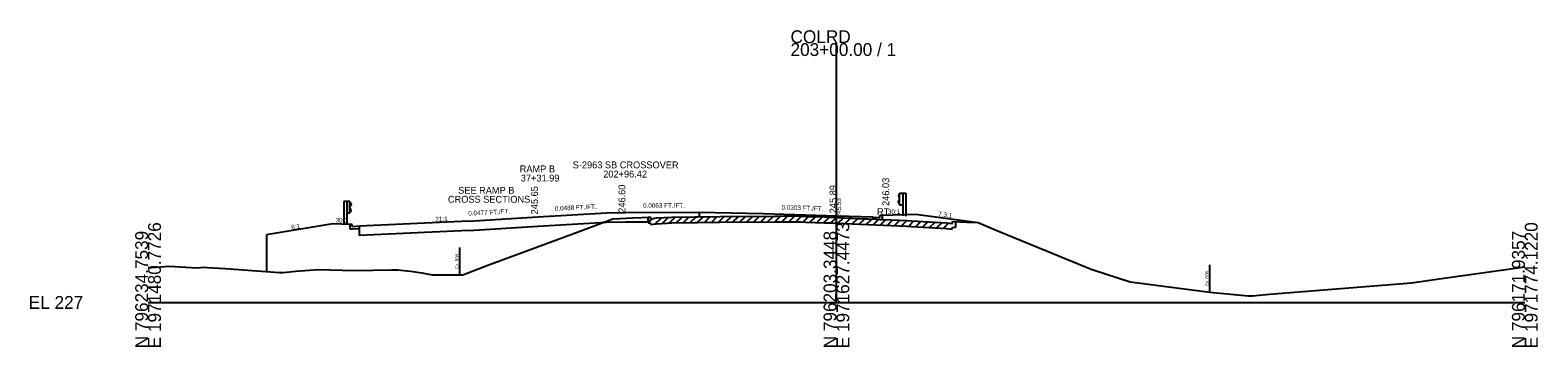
# Model space of a CAD drawing. Extents: x -26 to 1971520, y -10 to 796285.
# Drawn here: x 1274.3 to 1602.8, y 990.3 to 1059.4 of the extents above; entities that cross this region are included whole.
import ezdxf

# ---------------------------------------------------------------- set-up
doc = ezdxf.new("R2010")
doc.units = 0
for name, color, linetype in [('RD_GPK_XS_Cell', 7, 'Continuous'), ('RD_XS_Base', 7, 'Continuous'), ('RD_XS_CurbBase', 7, 'Continuous'), ('RD_XS_CurbTop', 7, 'Continuous'), ('RD_XS_ExGround', 7, 'Continuous'), ('RD_XS_ExPaveRet', 7, 'Continuous'), ('RD_XS_ExRW', 7, 'Continuous'), ('RD_XS_GR', 7, 'Continuous'), ('RD_XS_Misc_Line', 7, 'Continuous'), ('RD_XS_Pave', 7, 'Continuous'), ('RD_XS_PaveOvlay', 7, 'Continuous'), ('RD_XS_PaveShd', 7, 'Continuous'), ('RD_XS_TieSlope', 7, 'Continuous'), ('RD_XS_TX_Elev_EX', 7, 'Continuous'), ('RD_XS_TX_Elev_PR', 7, 'Continuous'), ('RD_XS_TX_MkPT', 7, 'Continuous'), ('RD_XS_TX_Notes', 7, 'Continuous'), ('RD_XS_TX_Profile', 7, 'Continuous'), ('RD_XS_TX_Slope', 7, 'Continuous'), ('RD_XS_TX_Station', 7, 'Continuous'), ('RD_XS_TX_TOC', 7, 'Continuous')]:
    doc.layers.add(name, color=color, linetype=linetype)

msp = doc.modelspace()

# ---------------------------------------------------------------- linework, layer by layer
at = {"layer": 'RD_GPK_XS_Cell'}
for p, q in [((1450, 1000), (1450, 1056.54)), ((1300, 1000), (1450, 1000)), ((1450, 1000), (1600, 1000))]:
    msp.add_line(p, q, dxfattribs=at)
at = {"layer": 'RD_XS_Base'}
for p, q in [((1458, 1018.62), (1458, 1018.64)), ((1458, 1018.12), (1458, 1018.62)), ((1345.99, 1016.6), (1345.99, 1016.62)), ((1345.99, 1016.1), (1345.99, 1016.6)), ((1345.99, 1016.6), (1345.99, 1014.56)), ((1369.9, 1015.7), (1345.99, 1014.56)), ((1369.9, 1015.7), (1384.96, 1016.61)), ((1384.96, 1016.61), (1399.89, 1017.51)), ((1399.89, 1017.51), (1404.01, 1017.56)), ((1404.01, 1017.56), (1408.95, 1017.59))]:
    msp.add_line(p, q, dxfattribs=at)
at = {"layer": 'RD_XS_CurbBase'}
for p, q in [((1460, 1019.04), (1460, 1018.04)), ((1343.99, 1017.02), (1343.99, 1016.02)), ((1343.99, 1016.02), (1344.57, 1016.02)), ((1344.57, 1016.02), (1345.99, 1016.1)), ((1459.42, 1018.04), (1458, 1018.12)), ((1460, 1018.04), (1459.42, 1018.04))]:
    msp.add_line(p, q, dxfattribs=at)
at = {"layer": 'RD_XS_CurbTop'}
for p, q in [((1458, 1018.64), (1458, 1018.62)), ((1458, 1018.62), (1459.42, 1018.54)), ((1459.42, 1018.54), (1459.5, 1019.04)), ((1459.5, 1019.04), (1460, 1019.04)), ((1344.49, 1017.02), (1343.99, 1017.02)), ((1344.57, 1016.52), (1344.49, 1017.02)), ((1345.99, 1016.6), (1344.57, 1016.52)), ((1345.99, 1016.62), (1345.99, 1016.6))]:
    msp.add_line(p, q, dxfattribs=at)
at = {"layer": 'RD_XS_ExGround'}
msp.add_lwpolyline([(1300, 1007.6), (1300.74, 1007.61), (1304.66, 1007.92), (1310.64, 1007.52), (1312.39, 1007.69), (1312.98, 1007.65), (1316.8, 1007.4), (1328.63, 1006.55), (1329.06, 1006.53), (1329.42, 1006.54), (1332.21, 1006.81), (1337.13, 1007.2), (1345.01, 1006.96), (1353.01, 1007.09), (1354.34, 1007.09), (1357.22, 1006.84), (1359.64, 1006.46), (1361.94, 1006.01), (1365.83, 1005.98), (1368.61, 1006), (1374.03, 1008.09), (1393.7, 1015.4), (1401.31, 1018.24), (1405.6, 1018.44), (1409.45, 1018.61), (1409.55, 1018.21), (1410.03, 1018.29), (1410.76, 1018.41), (1414.12, 1018.58), (1419.14, 1018.67), (1419.71, 1018.69), (1424.59, 1018.72), (1436.64, 1018.8), (1437.25, 1018.81), (1440.59, 1018.85), (1442.29, 1018.8), (1443.31, 1018.76), (1447.38, 1018.64), (1448.05, 1018.62), (1448.73, 1018.59), (1450, 1018.53), (1465.33, 1017.85), (1466.37, 1017.79), (1474.05, 1017.38), (1475.21, 1017.23), (1475.32, 1017.63), (1478.38, 1017.51), (1480.89, 1017.41), (1484.43, 1015.88), (1505.51, 1007.25), (1513.97, 1004.48), (1530.3, 1002.35), (1531.4, 1002.22), (1539.74, 1001.45), (1540.15, 1001.43), (1540.69, 1001.43), (1544.38, 1001.82), (1575.33, 1004.29), (1581.31, 1005.16), (1600, 1007.74)], dxfattribs=at)
at = {"layer": 'RD_XS_ExPaveRet'}
for p, q in [((1408.95, 1017.34), (1408.95, 1018.59)), ((1408.95, 1017.34), (1409.45, 1017.36)), ((1409.45, 1017.36), (1409.55, 1016.96)), ((1409.55, 1016.96), (1410.03, 1017.04)), ((1410.03, 1017.04), (1410.76, 1017.16)), ((1410.76, 1017.16), (1414.12, 1017.33)), ((1414.12, 1017.33), (1419.14, 1017.42)), ((1419.14, 1017.42), (1419.71, 1017.44)), ((1419.71, 1017.44), (1424.59, 1017.47)), ((1424.59, 1017.47), (1436.64, 1017.55)), ((1436.64, 1017.55), (1437.25, 1017.56)), ((1437.25, 1017.56), (1440.59, 1017.6)), ((1440.59, 1017.6), (1442.29, 1017.55)), ((1442.29, 1017.55), (1443.31, 1017.51)), ((1443.31, 1017.51), (1447.38, 1017.39)), ((1447.38, 1017.39), (1448.05, 1017.37)), ((1448.05, 1017.37), (1448.73, 1017.34)), ((1448.73, 1017.34), (1450, 1017.28)), ((1450, 1017.28), (1465.33, 1016.6)), ((1465.33, 1016.6), (1466.37, 1016.54)), ((1466.37, 1016.54), (1474.05, 1016.13)), ((1474.05, 1016.13), (1475.21, 1015.98)), ((1475.21, 1015.98), (1475.32, 1016.38)), ((1475.32, 1016.38), (1475.98, 1016.35)), ((1475.98, 1017.6), (1475.98, 1016.35))]:
    msp.add_line(p, q, dxfattribs=at)
at = {"layer": 'RD_XS_ExRW'}
for p, q in [((1367.83, 1011.99), (1367.83, 1005.99)), ((1531.26, 1008.23), (1531.26, 1002.23))]:
    msp.add_line(p, q, dxfattribs=at)
at = {"layer": 'RD_XS_GR'}
for p, q in [((1343.32, 1021.99), (1342.66, 1021.99)), ((1342.66, 1021.99), (1342.66, 1016.94)), ((1343.99, 1021.99), (1343.32, 1021.99)), ((1343.32, 1021.99), (1343.32, 1017.05)), ((1343.99, 1019.43), (1343.99, 1021.99)), ((1343.99, 1021.83), (1344.26, 1021.39)), ((1463.77, 1023.69), (1463.5, 1023.25)), ((1463.5, 1023.25), (1463.5, 1023.14)), ((1463.5, 1023.14), (1463.77, 1022.7)), ((1463.5, 1021.99), (1463.77, 1022.43)), ((1463.5, 1021.88), (1463.5, 1021.99)), ((1463.77, 1021.44), (1463.5, 1021.88)), ((1463.77, 1023.85), (1464.44, 1023.85)), ((1463.77, 1021.28), (1463.77, 1023.85)), ((1464.44, 1023.85), (1465.1, 1023.85)), ((1464.44, 1023.85), (1464.44, 1018.91)), ((1465.1, 1023.85), (1465.1, 1018.79)), ((1343.99, 1019.43), (1343.32, 1019.43)), ((1344.26, 1021.28), (1343.99, 1020.84)), ((1344.26, 1020.14), (1343.99, 1020.58)), ((1343.99, 1019.59), (1344.26, 1020.03)), ((1344.26, 1021.39), (1344.26, 1021.28)), ((1344.26, 1020.03), (1344.26, 1020.14)), ((1463.77, 1021.28), (1464.44, 1021.28))]:
    msp.add_line(p, q, dxfattribs=at)
at = {"layer": 'RD_XS_Misc_Line'}
for p, q in [((1410.49, 1017.12), (1411.87, 1018.47)), ((1412.02, 1017.23), (1413.36, 1018.54)), ((1413.55, 1017.3), (1414.87, 1018.59)), ((1415.09, 1017.35), (1416.39, 1018.62)), ((1416.62, 1017.37), (1417.92, 1018.65)), ((1418.15, 1017.4), (1419.46, 1018.68)), ((1419.68, 1017.44), (1420.97, 1018.7)), ((1421.22, 1017.45), (1422.5, 1018.71)), ((1422.75, 1017.46), (1424.04, 1018.72)), ((1424.28, 1017.47), (1425.57, 1018.73)), ((1425.82, 1017.48), (1427.1, 1018.74)), ((1427.35, 1017.49), (1428.63, 1018.75)), ((1428.88, 1017.5), (1430.17, 1018.76)), ((1430.41, 1017.51), (1431.7, 1018.77)), ((1431.95, 1017.52), (1433.23, 1018.78)), ((1433.48, 1017.53), (1434.77, 1018.79)), ((1435.01, 1017.54), (1436.3, 1018.8)), ((1436.54, 1017.55), (1437.84, 1018.82)), ((1438.08, 1017.57), (1439.37, 1018.83)), ((1439.61, 1017.59), (1440.89, 1018.84)), ((1441.14, 1017.58), (1442.39, 1018.8)), ((1442.68, 1017.53), (1443.91, 1018.74)), ((1444.21, 1017.48), (1445.45, 1018.7)), ((1445.74, 1017.44), (1446.98, 1018.65)), ((1447.27, 1017.4), (1448.51, 1018.6)), ((1448.81, 1017.34), (1450.03, 1018.53)), ((1450.34, 1017.27), (1451.56, 1018.46)), ((1408.95, 1017.34), (1409.9, 1018.27)), ((1451.87, 1017.2), (1453.09, 1018.39)), ((1453.41, 1017.13), (1454.63, 1018.33)), ((1454.94, 1017.06), (1456.16, 1018.26)), ((1456.47, 1016.99), (1457.69, 1018.19)), ((1458, 1016.93), (1459.23, 1018.12)), ((1459.54, 1016.86), (1460.76, 1018.05)), ((1461.07, 1016.79), (1462.29, 1017.98)), ((1462.6, 1016.72), (1463.82, 1017.92)), ((1464.14, 1016.65), (1465.36, 1017.85)), ((1465.67, 1016.58), (1466.88, 1017.77)), ((1467.2, 1016.5), (1468.41, 1017.68)), ((1468.73, 1016.42), (1469.94, 1017.6)), ((1470.27, 1016.33), (1471.48, 1017.52)), ((1471.8, 1016.25), (1473.01, 1017.44)), ((1473.33, 1016.17), (1474.51, 1017.32))]:
    msp.add_line(p, q, dxfattribs=at)
at = {"layer": 'RD_XS_Pave'}
for p, q in [((1369.9, 1017.74), (1384.96, 1018.65)), ((1384.96, 1018.65), (1399.89, 1019.55)), ((1404.01, 1019.6), (1420.07, 1019.7)), ((1420.07, 1019.7), (1420.07, 1018.69)), ((1434, 1019.38), (1450, 1018.89)), ((1450, 1018.89), (1458, 1018.64))]:
    msp.add_line(p, q, dxfattribs=at)
at = {"layer": 'RD_XS_PaveOvlay'}
for p, q in [((1408.95, 1018.59), (1409.45, 1018.61)), ((1408.95, 1018.59), (1408.95, 1017.59)), ((1409.45, 1018.61), (1409.55, 1018.21)), ((1410.76, 1018.41), (1414.12, 1018.58)), ((1414.12, 1018.58), (1419.14, 1018.67)), ((1419.14, 1018.67), (1419.71, 1018.69)), ((1419.71, 1018.69), (1424.59, 1018.72)), ((1424.59, 1018.72), (1436.64, 1018.8)), ((1436.64, 1018.8), (1437.25, 1018.81)), ((1437.25, 1018.81), (1440.59, 1018.85)), ((1440.59, 1018.85), (1442.29, 1018.8)), ((1442.29, 1018.8), (1443.31, 1018.76)), ((1443.31, 1018.76), (1447.38, 1018.64)), ((1447.38, 1018.64), (1448.05, 1018.62)), ((1448.05, 1018.62), (1448.73, 1018.59)), ((1448.73, 1018.59), (1450, 1018.53)), ((1450, 1018.53), (1458, 1018.18)), ((1409.55, 1018.21), (1410.03, 1018.29)), ((1410.03, 1018.29), (1410.76, 1018.41))]:
    msp.add_line(p, q, dxfattribs=at)
at = {"layer": 'RD_XS_PaveShd'}
for p, q in [((1399.89, 1019.55), (1404.01, 1019.6)), ((1420.07, 1019.7), (1434, 1019.38)), ((1369.9, 1017.74), (1345.99, 1016.6))]:
    msp.add_line(p, q, dxfattribs=at)
at = {"layer": 'RD_XS_TieSlope'}
for p, q in [((1460, 1019.04), (1467.25, 1019.28)), ((1467.25, 1019.28), (1480.89, 1017.41)), ((1340.24, 1017.14), (1325.84, 1014.74)), ((1343.99, 1017.02), (1340.24, 1017.14)), ((1325.84, 1014.74), (1325.84, 1006.75))]:
    msp.add_line(p, q, dxfattribs=at)

# ---------------------------------------------------------------- texts
at = {"layer": 'RD_GPK_XS_Cell'}
for s, p in [('COLRD', (1440, 1056.54)), ('203+00.00 / 1', (1440, 1053.74)), ('EL 227', (1274, 998.6))]:
    msp.add_text(s, height=2.8, dxfattribs=at).set_placement(p)
for s, p in [('N 796234.7539', (1300, 990)), ('E 1971480.7726', (1302.8, 990)), ('N 796203.3448', (1450, 990)), ('E 1971627.4473', (1452.8, 990)), ('N 796171.9357', (1600, 990)), ('E 1971774.1220', (1602.8, 990))]:
    msp.add_text(s, height=2.8, rotation=90, dxfattribs=at).set_placement(p)
at = {"layer": 'RD_XS_ExRW'}
for p in [(1367.58, 1007.38), (1531.01, 1003.62)]:
    msp.add_text('Ex. R/W ', height=0.65, rotation=90, dxfattribs=at).set_placement(p)
at = {"layer": 'RD_XS_TX_Elev_EX'}
msp.add_text('245.53', height=1, rotation=90, dxfattribs=at).set_placement((1451, 1018.53))
at = {"layer": 'RD_XS_TX_Elev_PR'}
for s, p in [(' 245.65', (1384.96, 1018.65)), (' 246.60', (1404.01, 1018.99)), (' 245.89', (1450, 1018.89))]:
    msp.add_text(s, height=1.5, rotation=90, dxfattribs=at).set_placement(p)
at = {"layer": 'RD_XS_TX_MkPT'}
msp.add_text('RT', height=1.5, dxfattribs=at).set_placement((1458.85, 1019.04))
at = {"layer": 'RD_XS_TX_Notes'}
for s, p in [('SEE RAMP B ', (1367.57, 1023.7)), ('CROSS SECTIONS', (1365.34, 1021.74))]:
    msp.add_text(s, height=1.5, dxfattribs=at).set_placement(p)
at = {"layer": 'RD_XS_TX_Profile'}
msp.add_text('21:1', height=1, rotation=2.731, dxfattribs=at).set_placement((1362.63, 1017.65))
at = {"layer": 'RD_XS_TX_Slope'}
for s, rotation, p in [('30:1', 358.8542, (1340.83, 1017.45)), ('0.0477 FT./FT.', 2.731, (1369.79, 1018.93)), ('0.0488 FT./FT.', 2.7914, (1388.66, 1019.97)), ('0.0063 FT./FT.', 0.3617, (1407.85, 1020.63)), ('0.0303 FT./FT.', 358.263, (1438.03, 1020.25)), ('30:1', 1.1458, (1461.22, 1019.25)), ('7.3:1', 352.202, (1472.13, 1018.84)), ('6:1', 9.0732, (1331.28, 1015.89))]:
    msp.add_text(s, height=1, rotation=rotation, dxfattribs=at).set_placement(p)
at = {"layer": 'RD_XS_TX_Station'}
for s, p in [('RAMP B', (1380.99, 1028.37)), ('S-2963 SB CROSSOVER', (1392.53, 1029.24)), ('202+96.42', (1399.18, 1027.24)), ('37+31.99', (1381.22, 1026.37))]:
    msp.add_text(s, height=1.5, dxfattribs=at).set_placement(p)
at = {"layer": 'RD_XS_TX_TOC'}
msp.add_text('246.03', height=1.5, rotation=90, dxfattribs=at).set_placement((1461.5, 1021.04))

doc.saveas('drawing.dxf')
